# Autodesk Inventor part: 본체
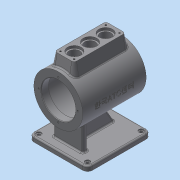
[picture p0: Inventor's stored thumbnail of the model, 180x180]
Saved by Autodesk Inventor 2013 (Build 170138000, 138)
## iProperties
Created: 2015-11
Part Number: 본체
Material: 알루미늄 6061
Document SubType Name: Modeling
Designer: mduedu
Density: 2.71 g/cm^3
Mass: 1557.05 g
Surface Area: 1415.53 cm^2
Volume: 574.557 cm^3
Author: mduedu
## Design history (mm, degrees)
sketch "스케치2"
  geometry: C1 r 50 at (0, 0); 1 further point
  constraints: 1 centre point, 1 coincident
  dimensions: "d147" = 100 diameter of C1
extrude "돌출1" new body sketch "스케치2" stored distance "d12" = 130; taper "d13" = 0 deg
feature "쉘1" dims "d31" = 15, "d32" = 6, "d33" = 15
sketch "스케치5"
  geometry: C1 r 35 at (0, 0); 1 further point
  constraints: 1 centre point, 1 coincident
  dimensions: "d34" = 70 diameter of C1
extrude "돌출3" cut sketch "스케치5" stored distance "d36" = 3; taper "d37" = 0 deg
node "작업 평면1"
sketch "스케치6"
  geometry: L1 (-65, -60)-(65, -60); L2 (65, -60)-(65, 60); L3 (65, 60)-(-65, 60); L4 (-65, 60)-(-65, -60); L5 (-65, -60)-(65, 60); L6 (65, -60)-(-65, 60); 1 further point
  constraints: 12 end point, 2 midpoint, 2 parallel, 1 horizontal, 1 perpendicular
  dimensions: "d41" = 120 distance of L3.end L1.start; "d43" = 130 distance of L2.end L3.end
extrude "돌출4" join sketch "스케치6" distance "d44" = 10; taper "d45" = 0 deg
sketch "스케치19"
  geometry: L1 (-45, 30)-(-35, 30); L2 (-35, 30)-(-35, -30); L3 (-35, -30)-(-45, -30); L4 (-45, -30)-(-45, 30); L5 (-65, 60)-(-65, -60) reference; 2 further points
  constraints: 8 end point, 2 parallel, 1 horizontal, 1 horizontal alignment, 1 midpoint, 1 perpendicular
  dimensions: "d150" = 20 distance between parallel lines of L4 L5; "d151" = 10 distance of L1.start L1.end; "d152" = 60 distance of L3.end L1.start
extrude "돌출9" join sketch "스케치19" stored distance "d153" = 10; taper "d154" = 0 deg
sketch "스케치20"
  geometry: L1 (65, 35)-(50, 35) reference; L2 (50, 35)-(50, 44) reference; L3 (50, 44)-(-50, 44) reference; L4 (-50, 44)-(-50, 35) reference; L5 (-50, 35)-(-65, 35) reference; L6 (-65, 35)-(-65, 50) reference; L7 (-65, 50)-(65, 50) reference; L8 (65, 50)-(65, 35) reference; L9 (50, -35)-(65, -35) reference; L10 (65, -35)-(65, -50) reference; L11 (65, -50)-(45, -50) reference; L12 (45, -50)-(45, -90) reference; L13 (45, -90)-(65, -90) reference; L14 (65, -90)-(65, -100) reference; L15 (65, -100)-(-65, -100) reference; L16 (-65, -100)-(-65, -90) reference; L17 (-65, -90)-(35, -90) reference; L18 (35, -90)-(35, -50) reference; L19 (35, -50)-(-65, -50) reference; L20 (-65, -50)-(-65, -35) reference; L21 (-65, -35)-(-50, -35) reference; L22 (-50, -35)-(-50, -44) reference; L23 (-50, -44)-(50, -44) reference; L24 (50, -44)-(50, -35) reference; L25 (-45, -90)-(-21.906, -50); 1 further point
  constraints: 2 end point, 2 point on line
  dimensions: "d155" = 20 distance from line of L25.start L16; "d156" = 120 deg angle of L25 L17
feature "리브2" sketch "스케치20" dims "d157" = 1, "d158" = 10, "d159" = 0, "d160" = 0, "d161" = 1, "d162" = 1
fillet "모깎기21" dims "d163" = 3
fillet "모깎기22" dims "d164" = 3
fillet "모깎기23" dims "d165" = 3
sketch "스케치21" dims "d166" = 80
  geometry: 3 further points
  constraints: 2 horizontal alignment, 1 coincident, 2 other
hole "구멍6" sketch "스케치21" at (40, 0) diameter "d168" = 3.242; stored, may be unused: countersink angle "d172" = 90 deg, drill point angle "d174" = 118 deg; dims "d169" = 9, "d170" = 4, "d171" = 2, "d173" = 11
node "작업 평면2"
sketch "스케치13"
  geometry: L1 (-52.5, -20)-(52.5, -20); L2 (52.5, -20)-(52.5, 20); L3 (52.5, 20)-(-52.5, 20); L4 (-52.5, 20)-(-52.5, -20); L5 (-52.5, -20)-(52.5, 20); L6 (52.5, -20)-(-52.5, 20); 1 further point
  constraints: 12 end point, 2 midpoint, 2 parallel, 1 horizontal, 1 perpendicular
  dimensions: "d93" = 105 distance of L2.end L3.end; "d95" = 40 distance of L1.end L2.end
extrude "돌출8" join sketch "스케치13" stored distance "d96" = 80; taper "d97" = 0 deg
fillet "모깎기15" dims "d98" = 5
feature "면 기울기1" dims angle "d178" = 10 deg
fillet "모깎기24" dims "d179" = 3
sketch "스케치14"
  geometry: L1 (-52.5, 15)-(-52.5, -15) reference; L2 (52.5, -15)-(52.5, 15) reference; L3 (-52.5, 0)-(52.5, 0); 4 further points
  constraints: 2 end point, 2 midpoint, 2 point on line, 1 coincident
  dimensions: "d100" = 32 distance of point (-32, 0) point (0, 0); "d102" = 32 distance of point (32, 0) point (0, 0) (derived)
hole "구멍3" sketch "스케치14" at (-32, 0), (0, 0), (32, 0) diameter "d103" = 22; stored, may be unused: countersink angle "d107" = 90 deg, drill point angle "d109" = 118 deg; dims "d104" = 8, "d105" = 28, "d106" = 5, "d108" = 10
sketch "스케치15"
  geometry: L1 (46.5, -14)-(-46.5, -14); L2 (-46.5, -14)-(-46.5, 14); L3 (-46.5, 14)-(46.5, 14); L4 (46.5, 14)-(46.5, -14); L5 (46.5, -14)-(-46.5, 14); L6 (-46.5, -14)-(46.5, 14); L7 (47.5, 20)-(-47.5, 20) reference; L8 (-52.5, 15)-(-52.5, -15) reference; 5 further points
  constraints: 12 end point, 4 coincident, 2 midpoint, 2 parallel, 1 horizontal, 1 perpendicular
  dimensions: "d110" = 6 distance between parallel lines of L3 L7; "d111" = 6 distance between parallel lines of L2 L8
hole "구멍4" sketch "스케치15" at (-46.5, 14), (46.5, 14), (46.5, -14), (-46.5, -14) diameter "d112" = 3.242; stored, may be unused: countersink angle "d116" = 90 deg, drill point angle "d118" = 118 deg; dims "d113" = 10, "d114" = 28, "d115" = 5, "d117" = 13
node "작업 평면3"
sketch "스케치22"
  geometry: 2 further points
  constraints: 1 coincident, 1 other
feature "엠보싱3" sketch "스케치22" dims "d32" = 6, "d181" = 0.5, "d182" = 0
chamfer "모따기2" distance "d183" = 1; stored, may be unused: second distance "d184" = 2, angle "d185" = 45 deg
fillet "모깎기25" dims "d186" = 10
sketch "스케치23"
  geometry: L1 (55, 60)-(-55, 60) reference; L2 (65, -50)-(65, 50) reference; L3 (-55, -60)-(55, -60) reference; L4 (-65, 50)-(-65, -50) reference; A1 r 10 centre (-55, 50) between (-55, 60) and (-65, 50) reference; A2 r 10 centre (55, 50) between (65, 50) and (55, 60) reference; A3 r 10 centre (55, -50) between (55, -60) and (65, -50) reference; A4 r 10 centre (-55, -50) between (-65, -50) and (-55, -60) reference; 1 further point
hole "구멍7" sketch "스케치23" at (-55, 50), (-55, -50), (55, -50), (55, 50) diameter "d187" = 6; stored, may be unused: countersink angle "d191" = 90 deg, drill point angle "d193" = 118 deg; dims "d188" = 9, "d189" = 10, "d190" = 2, "d192" = 11
fillet "모깎기26" dims "d194" = 3
node "솔리드1"
pattern_circular "원형 패턴2" dims angle "d176" = 360 deg
mirror "대칭5"
node "투영된 루프2"
node "절단 모서리 투영1"
